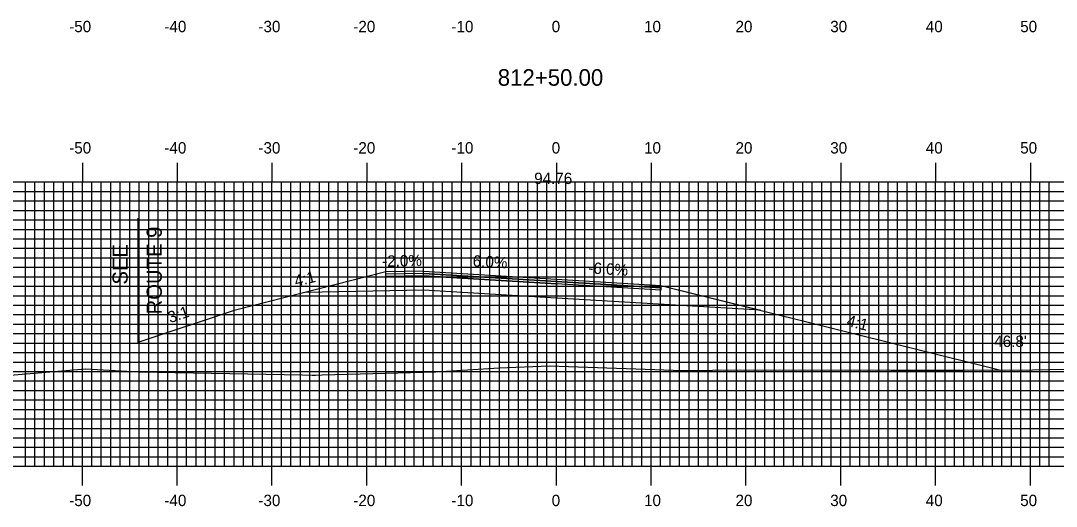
# Model space of a CAD drawing. Extents: x 2059 to 2403, y -1658 to -1438.
# Drawn here: x 2168.7 to 2277.9, y -1548.8 to -1497.6 of the extents above; entities that cross this region are included whole.
import ezdxf

# ---------------------------------------------------------------- set-up
doc = ezdxf.new("R2010")
doc.units = 0
for name, color, linetype in [('ANNOTATION', 7, 'Continuous'), ('D_Roadway_Centerline_Text', 7, 'Continuous'), ('D_Roadway_Edge_Shoulder', 7, 'Continuous'), ('D_Roadway_Edge_TW', 7, 'Continuous'), ('D_Roadway_Pavement', 7, 'Continuous'), ('D_Roadway_SlopeLines', 7, 'Continuous'), ('D_Roadway_SubGrade', 7, 'Continuous'), ('D_Text_Standard', 7, 'Continuous'), ('H_V ANNOTATION', 7, 'Continuous'), ('MAJOR', 7, 'Continuous'), ('MINOR', 7, 'Continuous'), ('S_Roadway_Centerline', 7, 'Continuous')]:
    doc.layers.add(name, color=color, linetype=linetype)

msp = doc.modelspace()

# ---------------------------------------------------------------- linework, layer by layer
at = {"layer": 'ANNOTATION'}
for p, q in [((2211.19, -1524.01), (2207.19, -1524.09)), ((2211.19, -1524.26), (2207.19, -1524.34)), ((2211.19, -1526.01), (2198.68, -1526.26))]:
    msp.add_line(p, q, dxfattribs=at)
msp.add_lwpolyline([(2211.19, -1524.51), (2207.19, -1524.59), (2207.19, -1524.09)], dxfattribs=at)
at = {"layer": 'D_Roadway_Edge_Shoulder'}
for points in [[(2225.19, -1524.85), (2236.22, -1525.51), (2236.22, -1525.76), (2225.19, -1525.1)], [(2225.19, -1525.1), (2236.22, -1525.76), (2236.22, -1526.01), (2225.19, -1525.35)]]:
    msp.add_lwpolyline(points, close=True, dxfattribs=at)
at = {"layer": 'D_Roadway_Edge_TW'}
msp.add_lwpolyline([(2211.19, -1524.01), (2225.19, -1524.85), (2225.19, -1525.1), (2211.19, -1524.26)], close=True, dxfattribs=at)
at = {"layer": 'D_Roadway_Pavement'}
msp.add_lwpolyline([(2211.19, -1524.26), (2225.19, -1525.1), (2225.19, -1525.35), (2211.19, -1524.51)], close=True, dxfattribs=at)
msp.add_lwpolyline([(2225.19, -1525.1), (2225.19, -1525.35)], dxfattribs=at)
msp.add_lwpolyline([(2225.19, -1525.1), (2225.19, -1525.35)], dxfattribs=at)
at = {"layer": 'D_Roadway_SlopeLines'}
msp.add_lwpolyline([(2236.22, -1525.51), (2271.94, -1534.44)], dxfattribs=at)
at = {"layer": 'D_Roadway_SubGrade'}
msp.add_line((2181.04, -1518.41), (2181.04, -1531.55), dxfattribs=at)
msp.add_lwpolyline([(2207.19, -1524.09), (2191.19, -1528.17), (2181.04, -1531.55)], dxfattribs=at)
for points in [[(2211.19, -1524.51), (2225.19, -1525.35), (2225.19, -1526.85), (2211.19, -1526.01)], [(2225.19, -1525.35), (2225.19, -1525.1), (2236.22, -1525.76), (2236.22, -1525.51), (2246.74, -1528.14), (2225.19, -1526.85)]]:
    msp.add_lwpolyline(points, close=True, dxfattribs=at)
at = {"layer": 'MAJOR'}
for p, q in [((2175.19, -1512.6), (2175.19, -1514.6)), ((2185.19, -1512.6), (2185.19, -1514.6)), ((2195.19, -1512.6), (2195.19, -1514.6)), ((2205.19, -1512.6), (2205.19, -1514.6)), ((2215.19, -1512.6), (2215.19, -1514.6)), ((2225.19, -1512.6), (2225.19, -1514.6)), ((2235.19, -1512.6), (2235.19, -1514.6)), ((2245.19, -1512.6), (2245.19, -1514.6)), ((2255.19, -1512.6), (2255.19, -1514.6)), ((2265.19, -1512.6), (2265.19, -1514.6)), ((2275.19, -1512.6), (2275.19, -1514.6)), ((2085.19, -1514.6), (2365.19, -1514.6)), ((2085.19, -1514.6), (2365.19, -1514.6)), ((2175.19, -1544.6), (2175.19, -1514.6)), ((2185.19, -1544.6), (2185.19, -1514.6)), ((2195.19, -1544.6), (2195.19, -1514.6)), ((2205.19, -1544.6), (2205.19, -1514.6)), ((2215.19, -1544.6), (2215.19, -1514.6)), ((2225.19, -1544.6), (2225.19, -1514.6)), ((2235.19, -1544.6), (2235.19, -1514.6)), ((2245.19, -1544.6), (2245.19, -1514.6)), ((2255.19, -1544.6), (2255.19, -1514.6)), ((2265.19, -1544.6), (2265.19, -1514.6)), ((2275.19, -1544.6), (2275.19, -1514.6)), ((2085.19, -1519.6), (2365.19, -1519.6)), ((2085.19, -1524.6), (2365.19, -1524.6)), ((2085.19, -1529.6), (2365.19, -1529.6)), ((2085.19, -1534.6), (2365.19, -1534.6)), ((2085.19, -1539.6), (2365.19, -1539.6)), ((2085.19, -1544.6), (2365.19, -1544.6)), ((2085.19, -1544.6), (2365.19, -1544.6)), ((2175.19, -1546.61), (2175.19, -1544.6)), ((2185.19, -1546.61), (2185.19, -1544.6)), ((2195.19, -1546.61), (2195.19, -1544.6)), ((2205.19, -1546.61), (2205.19, -1544.6)), ((2215.19, -1546.61), (2215.19, -1544.6)), ((2225.19, -1546.61), (2225.19, -1544.6)), ((2235.19, -1546.61), (2235.19, -1544.6)), ((2245.19, -1546.61), (2245.19, -1544.6)), ((2255.19, -1546.61), (2255.19, -1544.6)), ((2265.19, -1546.61), (2265.19, -1544.6)), ((2275.19, -1546.61), (2275.19, -1544.6))]:
    msp.add_line(p, q, dxfattribs=at)
at = {"layer": 'MINOR'}
for p, q in [((2169.19, -1544.6), (2169.19, -1514.6)), ((2170.19, -1544.6), (2170.19, -1514.6)), ((2171.19, -1544.6), (2171.19, -1514.6)), ((2172.19, -1544.6), (2172.19, -1514.6)), ((2173.19, -1544.6), (2173.19, -1514.6)), ((2174.19, -1544.6), (2174.19, -1514.6)), ((2176.19, -1544.6), (2176.19, -1514.6)), ((2177.19, -1544.6), (2177.19, -1514.6)), ((2178.19, -1544.6), (2178.19, -1514.6)), ((2179.19, -1544.6), (2179.19, -1514.6)), ((2180.19, -1544.6), (2180.19, -1514.6)), ((2181.19, -1544.6), (2181.19, -1514.6)), ((2182.19, -1544.6), (2182.19, -1514.6)), ((2183.19, -1544.6), (2183.19, -1514.6)), ((2184.19, -1544.6), (2184.19, -1514.6)), ((2186.19, -1544.6), (2186.19, -1514.6)), ((2187.19, -1544.6), (2187.19, -1514.6)), ((2188.19, -1544.6), (2188.19, -1514.6)), ((2189.19, -1544.6), (2189.19, -1514.6)), ((2190.19, -1544.6), (2190.19, -1514.6)), ((2191.19, -1544.6), (2191.19, -1514.6)), ((2192.19, -1544.6), (2192.19, -1514.6)), ((2193.19, -1544.6), (2193.19, -1514.6)), ((2194.19, -1544.6), (2194.19, -1514.6)), ((2196.19, -1544.6), (2196.19, -1514.6)), ((2197.19, -1544.6), (2197.19, -1514.6)), ((2198.19, -1544.6), (2198.19, -1514.6)), ((2199.19, -1544.6), (2199.19, -1514.6)), ((2200.19, -1544.6), (2200.19, -1514.6)), ((2201.19, -1544.6), (2201.19, -1514.6)), ((2202.19, -1544.6), (2202.19, -1514.6)), ((2203.19, -1544.6), (2203.19, -1514.6)), ((2204.19, -1544.6), (2204.19, -1514.6)), ((2206.19, -1544.6), (2206.19, -1514.6)), ((2207.19, -1544.6), (2207.19, -1514.6)), ((2208.19, -1544.6), (2208.19, -1514.6)), ((2209.19, -1544.6), (2209.19, -1514.6)), ((2210.19, -1544.6), (2210.19, -1514.6)), ((2211.19, -1544.6), (2211.19, -1514.6)), ((2212.19, -1544.6), (2212.19, -1514.6)), ((2213.19, -1544.6), (2213.19, -1514.6)), ((2214.19, -1544.6), (2214.19, -1514.6)), ((2216.19, -1544.6), (2216.19, -1514.6)), ((2217.19, -1544.6), (2217.19, -1514.6)), ((2218.19, -1544.6), (2218.19, -1514.6)), ((2219.19, -1544.6), (2219.19, -1514.6)), ((2220.19, -1544.6), (2220.19, -1514.6)), ((2221.19, -1544.6), (2221.19, -1514.6)), ((2222.19, -1544.6), (2222.19, -1514.6)), ((2223.19, -1544.6), (2223.19, -1514.6)), ((2224.19, -1544.6), (2224.19, -1514.6)), ((2226.19, -1544.6), (2226.19, -1514.6)), ((2227.19, -1544.6), (2227.19, -1514.6)), ((2228.19, -1544.6), (2228.19, -1514.6)), ((2229.19, -1544.6), (2229.19, -1514.6)), ((2230.19, -1544.6), (2230.19, -1514.6)), ((2231.19, -1544.6), (2231.19, -1514.6)), ((2232.19, -1544.6), (2232.19, -1514.6)), ((2233.19, -1544.6), (2233.19, -1514.6)), ((2234.19, -1544.6), (2234.19, -1514.6)), ((2236.19, -1544.6), (2236.19, -1514.6)), ((2237.19, -1544.6), (2237.19, -1514.6)), ((2238.19, -1544.6), (2238.19, -1514.6)), ((2239.19, -1544.6), (2239.19, -1514.6)), ((2240.19, -1544.6), (2240.19, -1514.6)), ((2241.19, -1544.6), (2241.19, -1514.6)), ((2242.19, -1544.6), (2242.19, -1514.6)), ((2243.19, -1544.6), (2243.19, -1514.6)), ((2244.19, -1544.6), (2244.19, -1514.6)), ((2246.19, -1544.6), (2246.19, -1514.6)), ((2247.19, -1544.6), (2247.19, -1514.6)), ((2248.19, -1544.6), (2248.19, -1514.6)), ((2249.19, -1544.6), (2249.19, -1514.6)), ((2250.19, -1544.6), (2250.19, -1514.6)), ((2251.19, -1544.6), (2251.19, -1514.6)), ((2252.19, -1544.6), (2252.19, -1514.6)), ((2253.19, -1544.6), (2253.19, -1514.6)), ((2254.19, -1544.6), (2254.19, -1514.6)), ((2256.19, -1544.6), (2256.19, -1514.6)), ((2257.19, -1544.6), (2257.19, -1514.6)), ((2258.19, -1544.6), (2258.19, -1514.6)), ((2259.19, -1544.6), (2259.19, -1514.6)), ((2260.19, -1544.6), (2260.19, -1514.6)), ((2261.19, -1544.6), (2261.19, -1514.6)), ((2262.19, -1544.6), (2262.19, -1514.6)), ((2263.19, -1544.6), (2263.19, -1514.6)), ((2264.19, -1544.6), (2264.19, -1514.6)), ((2266.19, -1544.6), (2266.19, -1514.6)), ((2267.19, -1544.6), (2267.19, -1514.6)), ((2268.19, -1544.6), (2268.19, -1514.6)), ((2269.19, -1544.6), (2269.19, -1514.6)), ((2270.19, -1544.6), (2270.19, -1514.6)), ((2271.19, -1544.6), (2271.19, -1514.6)), ((2272.19, -1544.6), (2272.19, -1514.6)), ((2273.19, -1544.6), (2273.19, -1514.6)), ((2274.19, -1544.6), (2274.19, -1514.6)), ((2276.19, -1544.6), (2276.19, -1514.6)), ((2277.19, -1544.6), (2277.19, -1514.6)), ((2085.19, -1515.6), (2365.19, -1515.6)), ((2085.19, -1516.6), (2365.19, -1516.6)), ((2085.19, -1517.6), (2365.19, -1517.6)), ((2085.19, -1518.6), (2365.19, -1518.6)), ((2085.19, -1520.6), (2365.19, -1520.6)), ((2085.19, -1521.6), (2365.19, -1521.6)), ((2085.19, -1522.6), (2365.19, -1522.6)), ((2085.19, -1523.6), (2365.19, -1523.6)), ((2085.19, -1525.6), (2365.19, -1525.6)), ((2085.19, -1526.6), (2365.19, -1526.6)), ((2085.19, -1527.6), (2365.19, -1527.6)), ((2085.19, -1528.6), (2365.19, -1528.6)), ((2085.19, -1530.6), (2365.19, -1530.6)), ((2085.19, -1531.6), (2365.19, -1531.6)), ((2085.19, -1532.6), (2365.19, -1532.6)), ((2085.19, -1533.6), (2365.19, -1533.6)), ((2085.19, -1535.6), (2365.19, -1535.6)), ((2085.19, -1536.6), (2365.19, -1536.6)), ((2085.19, -1537.6), (2365.19, -1537.6)), ((2085.19, -1538.6), (2365.19, -1538.6)), ((2085.19, -1540.6), (2365.19, -1540.6)), ((2085.19, -1541.6), (2365.19, -1541.6)), ((2085.19, -1542.6), (2365.19, -1542.6)), ((2085.19, -1543.6), (2365.19, -1543.6))]:
    msp.add_line(p, q, dxfattribs=at)
at = {"layer": 'S_Roadway_Centerline'}
msp.add_lwpolyline([(2165.87, -1535.12), (2175.52, -1534.33), (2181.14, -1534.65), (2198.41, -1534.94), (2199.44, -1534.98), (2199.79, -1534.97), (2200.47, -1534.96), (2212.48, -1534.65), (2219.14, -1534.2), (2224.47, -1534), (2235.59, -1534.39), (2238.45, -1534.49), (2241.66, -1534.47), (2256.15, -1534.41), (2260.46, -1534.46), (2268.09, -1534.45), (2275.41, -1534.43), (2284.59, -1534.24)], dxfattribs=at)

# ---------------------------------------------------------------- texts
at = {"layer": 'ANNOTATION'}
for s, height, rotation, p in [('ROUTE 9', 1.6, 90, (2183.57, -1528.58)), ('SEE', 1.6, 90, (2179.97, -1525.43)), ('-2.0%', 1.2, 1.1458, (2206.82, -1523.56)), ('6.0%', 1.2, 356.5664, (2216.34, -1523.51)), ('-6.0%', 1.2, 356.5664, (2228.54, -1524.25)), ('4:1', 1.2, 14.0362, (2197.72, -1525.67)), ('3:1', 1.2, 18.4348, (2184.45, -1529.5)), ('4:1', 1.2, 345.9638, (2255.74, -1529.77))]:
    msp.add_text(s, height=height, rotation=rotation, dxfattribs=at).set_placement(p)
at = {"layer": 'D_Roadway_Centerline_Text'}
msp.add_text('94.76', height=1.2, dxfattribs=at).set_placement((2222.85, -1514.82))
at = {"layer": 'D_Text_Standard'}
msp.add_text("46.8'", height=1.2, dxfattribs=at).set_placement((2271.38, -1532.01))
at = {"layer": 'H_V ANNOTATION'}
for s, height, p in [('-50', 1.2, (2173.8, -1498.8)), ('-40', 1.2, (2183.84, -1498.8)), ('-30', 1.2, (2193.76, -1498.8)), ('-20', 1.2, (2203.77, -1498.8)), ('-10', 1.2, (2214.12, -1498.8)), ('0', 1.2, (2224.7, -1498.8)), ('10', 1.2, (2234.44, -1498.8)), ('20', 1.2, (2244.09, -1498.8)), ('30', 1.2, (2254.08, -1498.8)), ('40', 1.2, (2264.16, -1498.8)), ('50', 1.2, (2274.12, -1498.8)), ('812+50.00', 1.75, (2219.01, -1504.45)), ('-50', 1.2, (2173.8, -1511.6)), ('-40', 1.2, (2183.84, -1511.6)), ('-30', 1.2, (2193.76, -1511.6)), ('-20', 1.2, (2203.77, -1511.6)), ('-10', 1.2, (2214.12, -1511.6)), ('0', 1.2, (2224.7, -1511.6)), ('10', 1.2, (2234.44, -1511.6)), ('20', 1.2, (2244.09, -1511.6)), ('30', 1.2, (2254.08, -1511.6)), ('40', 1.2, (2264.16, -1511.6)), ('50', 1.2, (2274.12, -1511.6)), ('-50', 1.2, (2173.8, -1548.8)), ('-40', 1.2, (2183.84, -1548.8)), ('-30', 1.2, (2193.76, -1548.8)), ('-20', 1.2, (2203.77, -1548.8)), ('-10', 1.2, (2214.12, -1548.8)), ('0', 1.2, (2224.7, -1548.8)), ('10', 1.2, (2234.44, -1548.8)), ('20', 1.2, (2244.09, -1548.8)), ('30', 1.2, (2254.08, -1548.8)), ('40', 1.2, (2264.16, -1548.8)), ('50', 1.2, (2274.12, -1548.8))]:
    msp.add_text(s, height=height, dxfattribs=at).set_placement(p)

doc.saveas('drawing.dxf')
